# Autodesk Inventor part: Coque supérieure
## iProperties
Created: 2010-07
Part Number: Coque supérieure
Document SubType Name: Modeling
Designer: eric
Density: 1 g/cm^3
Mass: 7.00211 g
Surface Area: 146.578 cm^2
Volume: 7.00211 cm^3
Author: eric
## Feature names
1. Base1
2. Extrusion32
3. Extrusion31
4. Extrusion30
5. Chamfer2
6. Extrusion29
7. Extrusion28
8. Extrusion27
9. Extrusion26
10. Extrusion25
11. Chamfer1
12. Extrusion24
13. Extrusion23
14. Extrusion22
15. Extrusion21
16. Extrusion20
17. Extrusion19
18. Extrusion18
19. Extrusion17
20. Extrusion16
21. Extrusion15
22. Extrusion14
23. Extrusion13
24. Extrusion12
25. Extrusion11
26. Extrusion10
27. Extrusion9
28. Extrusion8
29. Extrusion7
30. Extrusion6
31. Extrusion5
32. Extrusion4
33. Extrusion3
34. Extrusion2
35. Extrusion1
36. Fillet2
37. Fillet1
